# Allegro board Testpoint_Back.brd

Outline 100 x 50 mm; copper layers: TOP, POWERPLANE_1, BOTTOM. Coordinates in mm from the lower left corner of the outline.
Outline path: rectangle 0,0 100,50

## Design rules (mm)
constraint set DEFAULT: min track width 0.28
net group DPD: nets D+ D-

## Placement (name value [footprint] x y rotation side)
C1  100uF  [1210]  9 28 0 top
C2  10uF  [0402-CAP]  15 35 270 top
C3  10uF  [0402-CAP]  34 8 180 top
C4  0.1uF  [0402-CAP]  6 23 0 top
C5  0.1uF  [0402-CAP]  6 20 0 top
C6  0.1uF  [0402-CAP]  8 40 90 top
C7  0.1uF  [0402-CAP]  36 16 90 top
C8  0.1uF  [0402-CAP]  5 40 90 top
C9  10uF  [0402-CAP]  15 24 180 top
IC1  PIC32MX440F512H  [SQFP-S-10X10-64]  24 26 90 top
JP1  -  [XTEND-DIGI-MODEM]  69 25 0 top
JP2  PIC 32 PROG  [1X06_LOCK]  12.7 14.61 0 top
MAIN_PWR  LED  [LED_LNJ]  24 4 90 top
NOREF  -  []  0 50 0 top
NOREF#2  -  []  0 0 90 top
NOREF#3  -  [unnamed#2]  96 4 0 top
NOREF#4  -  []  0 0 0 top
NOREF#5  -  [unnamed#2]  96 46 0 top
NOREF#6  -  []  -23 -96 0 top
NOREF#7  -  [unnamed#2]  4 46 0 top
NOREF#8  -  []  0 0 0 top
NOREF#9  -  [unnamed#2]  4 4 0 top
R1  150  [0402-RES]  20 4 90 top
R2  56k  [0402-RES]  34 11 180 top
U1  LT1965EMS8E-1P5TRPBF  [MSOP-EP08_3X3_ADI]  9 34 0 top
X1  USB-B  [USB-MICROB]  20 46 180 top
Y1  8MHz  [CRYSTAL-SMD]  20 38 270 top

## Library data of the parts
C1-C9 = CAP NP
IC1 = PIC32MX440F512H
JP1 = XTEND-DIGI-MODEM
JP2 = M06_LOCK
MAIN_PWR = LED
R1 R2 = RESISTOR
U1 = LT1965EMS8E-1P5TRPBF_0
X1 = USB-MICROB
Y1 = CRYSTAL

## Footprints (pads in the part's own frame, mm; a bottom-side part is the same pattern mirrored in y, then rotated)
1X06_LOCK
  round 1.88 hole 1.016: 1(0,0) 2(2.54,-0.254) 3(5.08,0) 4(7.62,-0.254) 5(10.16,0) 6(12.7,-0.254)
0402-CAP
  rect 0.7x0.9 smd: 1(-0.65,0) 2(0.65,0)
0402-RES
  rect 0.7x0.9 smd: 1(-0.65,0) 2(0.65,0)
1210
  rect 1.2x2 smd: 1(-1.6,0) 2(1.6,0)
CRYSTAL-SMD
  rect 1.1x1.9 smd: 1(-1.15,1.85) 2(-1.15,-1.85) 3(1.15,-1.85) 4(1.15,1.85)
LED_LNJ
  rect 0.445x0.95 smd: 1(-0.652,0) 2(0.652,0)
MSOP-EP08_3X3_ADI
  rect 1.397x0.432 smd: 1(-2.197,0.975) 2(-2.197,0.325) 3(-2.197,-0.325) 4(-2.197,-0.975) 5(2.197,-0.975) 6(2.197,-0.325) 7(2.197,0.325) 8(2.197,0.975)
  rect 1.676x1.88 smd: EPAD(0,0)
SQFP-S-10X10-64
  rect 1.6x0.295 smd: 1(-5.6,3.75) 2(-5.6,3.25) 3(-5.6,2.75) 4(-5.6,2.25) 5(-5.6,1.75) 6(-5.6,1.25) 7(-5.6,0.75) 8(-5.6,0.25) 9(-5.6,-0.25) 10(-5.6,-0.75) 11(-5.6,-1.25) 12(-5.6,-1.75) 13(-5.6,-2.25) 14(-5.6,-2.75) 15(-5.6,-3.25) 16(-5.6,-3.75) 33(5.6,-3.75) 34(5.6,-3.25) 35(5.6,-2.75) 36(5.6,-2.25) 37(5.6,-1.75) 38(5.6,-1.25) 39(5.6,-0.75) 40(5.6,-0.25) 41(5.6,0.25) 42(5.6,0.75) 43(5.6,1.25) 44(5.6,1.75) 45(5.6,2.25) 46(5.6,2.75) 47(5.6,3.25) 48(5.6,3.75)
  rect 0.295x1.6 smd: 17(-3.75,-5.6) 18(-3.25,-5.6) 19(-2.75,-5.6) 20(-2.25,-5.6) 21(-1.75,-5.6) 22(-1.25,-5.6) 23(-0.75,-5.6) 24(-0.25,-5.6) 25(0.25,-5.6) 26(0.75,-5.6) 27(1.25,-5.6) 28(1.75,-5.6) 29(2.25,-5.6) 30(2.75,-5.6) 31(3.25,-5.6) 32(3.75,-5.6) 49(3.75,5.6) 50(3.25,5.6) 51(2.75,5.6) 52(2.25,5.6) 53(1.75,5.6) 54(1.25,5.6) 55(0.75,5.6) 56(0.25,5.6) 57(-0.25,5.6) 58(-0.75,5.6) 59(-1.25,5.6) 60(-1.75,5.6) 61(-2.25,5.6) 62(-2.75,5.6) 63(-3.25,5.6) 64(-3.75,5.6)
unnamed#2
  round 4.064 hole 3.81: (0,0)
USB-MICROB
  rect 0.35x1.4 smd: D+(0,2.65) D-(-0.65,2.65) GND(1.3,2.65) ID(0.65,2.65) VBUS(-1.3,2.65)
  rect 1.8x1.9 smd: MT1(-3.8,0) MT2(3.8,0)
  rect 2.1x1.6 smd: MT3(-3.1,2.55) MT4(3.1,2.55)
  rect 1.9x1.9 smd: P_1(-1.2,0) P_2(1.2,0)
XTEND-DIGI-MODEM
  round 0 hole 3.3 unplated: (-26.5,14.5) (-26.5,-14.5) (26.5,14.5) (26.5,-14.5)
  round 1.422 hole 0.7: 1(-27.5,9) 2(-25.5,9) 3(-27.5,7) 4(-25.5,7) 5(-27.5,5) 6(-25.5,5) 7(-27.5,3) 8(-25.5,3) 9(-27.5,1) 10(-25.5,1) 11(-27.5,-1) 12(-25.5,-1) 13(-27.5,-3) 14(-25.5,-3) 15(-27.5,-5) 16(-25.5,-5) 17(-27.5,-7) 18(-25.5,-7) 19(-27.5,-9) 20(-25.5,-9)

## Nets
3.3V: C1.1 C4.1 C5.1 C6.1 C7.1 C8.1 IC1.10 IC1.19 IC1.26 IC1.35 IC1.38 JP2.2 R1.1 R2.2 U1.1 U1.2 U1.3
GND: C1.2 C2.2 C3.2 C4.2 C5.2 C6.2 C7.2 C8.2 C9.2 IC1.9 IC1.20 IC1.25 IC1.41 JP1.1 JP2.3 MAIN_PWR.1(CATHODE) U1.4 U1.5 U1.EPAD X1.GND Y1.2 Y1.4(GND_4)
VBUS: C2.1 IC1.34 JP1.2(VCC) U1.6(SHDN) U1.7 U1.8 X1.VBUS
CTS: IC1.21 JP1.9
D+: IC1.37 X1.D+
D-: IC1.36 X1.D-
PROG0: IC1.17 JP2.5
PROG1: IC1.18 JP2.4
RESET: IC1.7(_MCLR) JP2.1
RTS: IC1.29 JP1.10
SHDN: IC1.59 JP1.7
URX: IC1.31 JP1.6
UTX: IC1.32 JP1.5
N02210: C3.1 JP1.11 R2.1
N02258: IC1.39 Y1.1
N02262: IC1.40 Y1.3
N02281: C9.1 IC1.56
N02349: MAIN_PWR.2 R1.2

Pads without a net: IC1 1 2 3 4 5 6 8 11 12 13 14 15 16 22 23 24 27 28 30 33 42 43 44 45 46 47 48 49 50 51 52 53 54 55 57 58 60 61 62 63 64; JP1 3 4 8 12 13 14 15 16 17 18 19 20; JP2 6; X1 ID MT1 MT2 MT3 MT4 P_1 P_2

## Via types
v1: diameter 0.61, hole 0.33, TOP to BOTTOM, 34 vias

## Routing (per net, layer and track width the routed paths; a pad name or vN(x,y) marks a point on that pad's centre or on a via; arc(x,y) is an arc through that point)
3.3V: length 21.1
  TOP w0.28: IC1.19 v1(31.37,23.25) ; IC1.38 v1(25.25,32.83) ; IC1.35 v1(26.75,32.83) ; IC1.10 v1(24.75,18.63) ; IC1.26 v1(30.83,26.75)
  TOP w0.381: U1.1 6.31,34.98 ; 6.31,34.98 v1(5.67,34.98) ; 6.31,34.98 6.31,34.44 6.42,34.33 U1.2 U1.3 ; R1.1 v1(20,2.57) ; R2.2 v1(32.57,11) ; C1.1 v1(6.37,28) ; C5.1 v1(4.57,20) ; C7.1 v1(36,14.57) ; C8.1 v1(5,38.57) ; C4.1 v1(4.57,23) ; C6.1 v1(8,38.57)
  POWERPLANE_1 w0.381: JP2.2 16.36,14.35 ; JP2.2 14.12,14.35 ; JP2.2 15.24,13.23 ; JP2.2 15.24,15.47
GND: length 33.3
  TOP w0.28: IC1.9 v1(24.25,22.34) ; IC1.20 v1(26.27,23.75) ; IC1.25 v1(26.27,26.25) ; IC1.41 v1(23.75,29.96)
  TOP w0.381: MAIN_PWR.1 v1(24,2.69) ; C7.2 v1(36,17.43) ; C2.2 v1(15,33.57) ; C6.2 v1(8,41.43) ; U1.4 v1(5.67,33.02) ; C1.2 v1(11.63,28) ; Y1.4 v1(23.23,36.85) ; U1.EPAD v1(9,35.37) ; C8.2 v1(5,41.43) ; U1.5 v1(12.33,33.02) ; C3.2 v1(32.57,8) ; Y1.2 v1(18.15,40.13) ; C4.2 v1(7.43,23) ; C5.2 v1(7.43,20) ; C9.2 v1(13.57,24) ; X1.GND v1(18.7,42.22)
  BOTTOM w0.381: JP1.1 42.39,34 ; JP1.1 41.5,34.89 ; JP1.1 40.61,34 ; JP1.1 41.5,33.11 ; JP2.3 17.78,15.72 ; JP2.3 18.9,14.61 ; JP2.3 17.78,13.49 ; JP2.3 16.66,14.61
VBUS: length 56.2
  TOP w0.28: X1.VBUS 21.3,42.2 22.23,41.27 26.39,41.27 26.67,40.99 26.67,38.73 27.3,38.1 27.3,36.23 27.25,36.17 ; 27.25,36.17 27.25,33.14 27.32,33.07 27.32,31.67 IC1.34 27.25,29.95 26.69,29.39 21.13,29.39 15.72,34.81 15.72,35.03 15.1,35.65 C2.1 14.97,35.68 14.21,35.68 13.5,34.98 U1.8 U1.7 U1.6 ; 27.25,36.17 41.33,36.17 JP1.2
CTS: length 12.6
  TOP w0.28: JP1.9 34.37,26 32.62,24.25 IC1.21
D+: length 15.7
  TOP w0.127: IC1.37 25.75,32.59 25.87,32.72 25.87,37.63 22.86,40.64 20.32,40.64 20.2,40.76 20.2,42.26 20,42.46 X1.D+
D-: length 15.7
  TOP w0.127: X1.D- 20.65,42.46 20.45,42.26 20.45,40.89 22.97,40.89 26.13,37.73 26.13,32.72 26.25,32.59 IC1.36
PROG0: length 11.9
  TOP w0.28: JP2.5 23.5,15.24 23.5,15.88 24.13,16.51 26.67,16.51 29.6,19.44 IC1.17
PROG1: length 14.4
  TOP w0.28: IC1.18 28.77,22.75 28.53,22.51 28.53,19.64 26.67,17.78 23.75,17.78 JP2.4
RESET: length 13.4
  TOP w0.28: IC1.7 23.25,19.57 22.09,18.41 16.51,18.41 JP2.1
RTS: length 14.8
  TOP w0.28: IC1.29 30.67,28.25 31.94,26.98 42.52,26.98 JP1.10
SHDN: length 33.3
  TOP w0.28: IC1.59 22.96,24.75 29.19,30.98 43.91,30.98 44.48,30.41 44.48,29.59 43.86,28.98 43.09,28.98 42.12,28 JP1.7
URX: length 14.4
  TOP w0.28: IC1.31 30.67,29.25 30.9,29.02 42.52,29.02 JP1.6
UTX: length 12
  TOP w0.28: JP1.5 40.52,30 40.27,29.75 IC1.32
N02210: length 18.8
  TOP w0.28: C3.1 R2.1 34.65,17.15 JP1.11
N02258: length 9.5
  TOP w0.28: Y1.1 23.08,39.15 24.75,37.48 24.75,33.14 24.68,33.07 24.68,31.67 IC1.39
N02262: length 9.2
  TOP w0.28: Y1.3 19.66,36.85 22.86,33.66 23.85,33.66 24.25,33.26 IC1.40
N02281: length 4.2
  TOP w0.28: C9.1 16.27,24 17.33,25.07 17.33,26.01 17.57,26.25 IC1.56
N02349: length 4
  TOP w0.28: MAIN_PWR.2 20.72,4.65 20.72,4.65 R1.2

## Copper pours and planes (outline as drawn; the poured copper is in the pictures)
3.3V on POWERPLANE_1: 0.3,49.7 99.7,49.7 99.7,0.3 0.3,0.3
GND on BOTTOM: 0.3,49.7 99.7,49.7 99.7,0.3 0.3,0.3

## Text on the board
User.Comments: A | EMA Design Automation | 225 Tech Park Drive | Rochester, NY, 14623 | EMA-123 | 1 of 1
XSECTION_CHART: *  SURFACE | L1 TOP CONDUCTOR | *  DIELECTRIC | L2 POWERPLANE_1 PLANE | L3 BOTTOM CONDUCTOR | DESIGN CROSS SECTION CHART | ___________________________ | TOTAL THICKNESS 0.49784 MM | 1-3
DIMENSION: FIGURE | FINISHED_SIZE | 0.3302 | 0.7 | 1.016 | 3.81 | 3.3 | DRILL CHART: TOP to BOTTOM | ALL UNITS ARE IN MILLIMETERS | PLATED | NON-PLATED | QTY | 34 | 20 | 6 | 4
